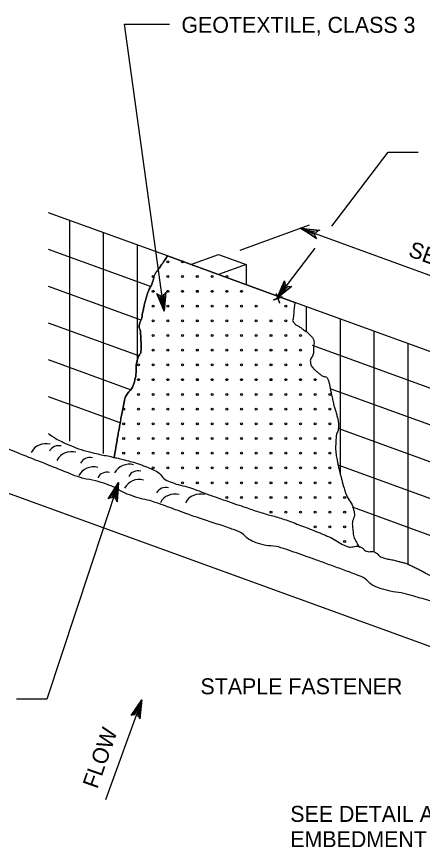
# Model space of a CAD drawing. Extents: x 636462 to 639049, y 299944 to 300538.
# Drawn here: x 636561.4 to 636637.5, y 300112.8 to 300268.7 of the extents above; entities that cross this region are included whole.
import ezdxf

# ---------------------------------------------------------------- set-up
doc = ezdxf.new("R2010")
doc.units = 0
doc.layers.add('Default', color=7, linetype='Continuous')

msp = doc.modelspace()

# ---------------------------------------------------------------- linework, layer by layer
at = {"layer": 'Default'}
for p, q in [((636589.69, 300223.81), (636567.43, 300231.91)), ((636571.32, 300230.5), (636571.32, 300189.06)), ((636571.32, 300230.5), (636571.32, 300230.5)), ((636603.35, 300224.92), (636616.34, 300229.64)), ((636577.67, 300228.19), (636577.67, 300186.75)), ((636577.67, 300228.19), (636577.67, 300228.19)), ((636584.01, 300225.88), (636584.01, 300203.89)), ((636584.01, 300225.88), (636584.01, 300225.88)), ((636586.55, 300218.05), (636567.43, 300225.01)), ((636613.62, 300215.1), (636589.69, 300223.81)), ((636589.69, 300223.81), (636613.62, 300215.1)), ((636590.36, 300223.57), (636590.36, 300223.57)), ((636596.71, 300221.26), (636596.71, 300221.26)), ((636604.5, 300222.2), (636604.5, 300218.42)), ((636584.79, 300211.78), (636567.43, 300218.1)), ((636603.05, 300218.95), (636603.05, 300218.95)), ((636609.4, 300216.64), (636609.4, 300216.64)), ((636689.45, 300187.5), (636613.62, 300215.1)), ((636615.75, 300214.33), (636615.75, 300209.52)), ((636615.75, 300214.33), (636615.75, 300214.33)), ((636622.09, 300212.02), (636622.09, 300182.98)), ((636622.09, 300212.02), (636622.09, 300212.02)), ((636584.34, 300205.04), (636567.43, 300211.19)), ((636628.44, 300209.71), (636628.44, 300168.26)), ((636628.44, 300209.71), (636628.44, 300209.71)), ((636689.45, 300180.59), (636616.89, 300207)), ((636634.79, 300207.4), (636634.79, 300165.96)), ((636634.79, 300207.4), (636634.79, 300207.4)), ((636582.75, 300198.71), (636567.43, 300204.29)), ((636689.45, 300173.69), (636620.24, 300198.88)), ((636580.84, 300192.5), (636567.43, 300197.38)), ((636689.45, 300166.78), (636621.71, 300191.44)), ((636689.45, 300159.87), (636621.74, 300184.52)), ((636673.8, 300137.8), (636559.57, 300179.37)), ((636689.45, 300152.97), (636624.4, 300176.65)), ((636584.92, 300140.52), (636578.08, 300121.72))]:
    msp.add_line(p, q, dxfattribs=at)
for points in [[(636589.08, 300213.44), (636581.64, 300267.32), (636590.08, 300267.32)], [(636620.53, 300229.41), (636631.08, 300243.32), (636636.75, 300243.32)], [(636614.68, 300229.04), (636645.53, 300217.77)], [(636617.5, 300227.34), (636617.67, 300227.03), (636614.68, 300229.04), (636617.5, 300227.34), (636617.44, 300227.75), (636614.68, 300229.04), (636617.61, 300228.25), (636617.91, 300228.54), (636614.68, 300229.04), (636618.27, 300228.68), (636617.91, 300228.54)], [(636610.23, 300215.82), (636617.41, 300225.29)], [(636612.72, 300217.99), (636613.06, 300218.07), (636610.23, 300215.82), (636612.72, 300217.99), (636612.3, 300218.06), (636610.23, 300215.82), (636611.88, 300218.38), (636611.7, 300218.75), (636610.23, 300215.82), (636611.67, 300219.13), (636611.7, 300218.75)], [(636589.25, 300216.73), (636589.43, 300217.03), (636589.08, 300213.44), (636589.25, 300216.73), (636588.91, 300216.49), (636589.08, 300213.44), (636588.39, 300216.41), (636587.99, 300216.53), (636589.08, 300213.44), (636587.7, 300216.78), (636587.99, 300216.53)], [(636580.53, 300181.28), (636567.1, 300140.64), (636561.43, 300140.64)], [(636578.9, 300178.42), (636578.6, 300178.24), (636580.53, 300181.28), (636578.9, 300178.42), (636579.31, 300178.49), (636580.53, 300181.28), (636579.81, 300178.33), (636580.11, 300178.03), (636580.53, 300181.28), (636580.26, 300177.69), (636580.11, 300178.03)], [(636583.2, 300137.71), (636582.9, 300137.54), (636584.92, 300140.52), (636583.2, 300137.71), (636583.62, 300137.77), (636584.92, 300140.52), (636584.11, 300137.59), (636584.4, 300137.29), (636584.92, 300140.52), (636584.54, 300136.94), (636584.4, 300137.29)]]:
    msp.add_lwpolyline(points, dxfattribs=at)
msp.add_lwpolyline([(636599.3, 300220.31), (636594.11, 300222.2), (636599.3, 300224.09), (636604.5, 300222.2)], close=True, dxfattribs=at)
for centre in [(636589.79, 300222.7), (636592.55, 300222.7), (636587.03, 300219.93), (636589.79, 300219.93), (636592.55, 300219.93), (636595.31, 300219.93), (636598.08, 300219.93), (636600.84, 300219.93), (636587.03, 300217.17), (636589.79, 300217.17), (636592.55, 300217.17), (636595.31, 300217.17), (636598.08, 300217.17), (636600.84, 300217.17), (636603.6, 300217.17), (636587.03, 300214.41), (636589.79, 300214.41), (636592.55, 300214.41), (636595.31, 300214.41), (636598.08, 300214.41), (636600.84, 300214.41), (636603.6, 300214.41), (636606.37, 300214.41), (636611.89, 300214.41), (636587.03, 300211.65), (636589.79, 300211.65), (636592.55, 300211.65), (636595.31, 300211.65), (636598.08, 300211.65), (636600.84, 300211.65), (636603.6, 300211.65), (636606.37, 300211.65), (636609.13, 300211.65), (636611.89, 300211.65), (636587.03, 300208.88), (636589.79, 300208.88), (636592.55, 300208.88), (636595.31, 300208.88), (636598.08, 300208.88), (636600.84, 300208.88), (636603.6, 300208.88), (636606.37, 300208.88), (636609.13, 300208.88), (636611.89, 300208.88), (636614.65, 300208.88), (636587.03, 300206.12), (636589.79, 300206.12), (636592.55, 300206.12), (636595.31, 300206.12), (636598.08, 300206.12), (636600.84, 300206.12), (636603.6, 300206.12), (636606.37, 300206.12), (636609.13, 300206.12), (636611.89, 300206.12), (636614.65, 300206.12), (636584.26, 300203.36), (636587.03, 300203.36), (636589.79, 300203.36), (636592.55, 300203.36), (636595.31, 300203.36), (636598.08, 300203.36), (636600.84, 300203.36), (636603.6, 300203.36), (636606.37, 300203.36), (636609.13, 300203.36), (636611.89, 300203.36), (636614.65, 300203.36), (636584.26, 300200.59), (636587.03, 300200.59), (636589.79, 300200.59), (636592.55, 300200.59), (636595.31, 300200.59), (636598.08, 300200.59), (636600.84, 300200.59), (636603.6, 300200.59), (636606.37, 300200.59), (636609.13, 300200.59), (636611.89, 300200.59), (636614.65, 300200.59), (636617.42, 300200.59), (636584.26, 300197.83), (636587.03, 300197.83), (636589.79, 300197.83), (636592.55, 300197.83), (636595.31, 300197.83), (636598.08, 300197.83), (636600.84, 300197.83), (636603.6, 300197.83), (636606.37, 300197.83), (636609.13, 300197.83), (636611.89, 300197.83), (636614.65, 300197.83), (636617.42, 300197.83), (636620.18, 300197.83), (636581.5, 300195.07), (636584.26, 300195.07), (636587.03, 300195.07), (636589.79, 300195.07), (636592.55, 300195.07), (636595.31, 300195.07), (636598.08, 300195.07), (636600.84, 300195.07), (636603.6, 300195.07), (636606.37, 300195.07), (636609.13, 300195.07), (636611.89, 300195.07), (636614.65, 300195.07), (636617.42, 300195.07), (636620.18, 300195.07), (636581.5, 300192.31), (636584.26, 300192.31), (636587.03, 300192.31), (636589.79, 300192.31), (636592.55, 300192.31), (636595.31, 300192.31), (636598.08, 300192.31), (636600.84, 300192.31), (636603.6, 300192.31), (636606.37, 300192.31), (636609.13, 300192.31), (636611.89, 300192.31), (636614.65, 300192.31), (636617.42, 300192.31), (636620.18, 300192.31), (636581.5, 300189.54), (636584.26, 300189.54), (636587.03, 300189.54), (636589.79, 300189.54), (636592.55, 300189.54), (636595.31, 300189.54), (636598.08, 300189.54), (636600.84, 300189.54), (636603.6, 300189.54), (636606.37, 300189.54), (636609.13, 300189.54), (636611.89, 300189.54), (636614.65, 300189.54), (636617.42, 300189.54), (636620.18, 300189.54), (636581.5, 300186.78), (636584.26, 300186.78), (636587.03, 300186.78), (636589.79, 300186.78), (636592.55, 300186.78), (636595.31, 300186.78), (636598.08, 300186.78), (636600.84, 300186.78), (636603.6, 300186.78), (636606.37, 300186.78), (636609.13, 300186.78), (636611.89, 300186.78), (636614.65, 300186.78), (636617.42, 300186.78), (636620.18, 300186.78), (636587.03, 300184.02), (636589.79, 300184.02), (636592.55, 300184.02), (636595.31, 300184.02), (636598.08, 300184.02), (636600.84, 300184.02), (636603.6, 300184.02), (636606.37, 300184.02), (636609.13, 300184.02), (636611.89, 300184.02), (636614.65, 300184.02), (636617.42, 300184.02), (636620.18, 300184.02), (636592.55, 300181.25), (636595.31, 300181.25), (636598.08, 300181.25), (636600.84, 300181.25), (636603.6, 300181.25), (636606.37, 300181.25), (636609.13, 300181.25), (636611.89, 300181.25), (636614.65, 300181.25), (636617.42, 300181.25), (636620.18, 300181.25), (636600.84, 300178.49), (636603.6, 300178.49), (636606.37, 300178.49), (636609.13, 300178.49), (636611.89, 300178.49), (636614.65, 300178.49), (636617.42, 300178.49), (636620.18, 300178.49), (636622.94, 300178.49), (636609.13, 300175.73), (636611.89, 300175.73), (636614.65, 300175.73), (636617.42, 300175.73), (636620.18, 300175.73), (636622.94, 300175.73), (636617.42, 300172.97), (636620.18, 300172.97), (636622.94, 300172.97), (636622.94, 300170.2)]:
    msp.add_circle(centre, 0.184, dxfattribs=at)
for centre, radius, start, end in [((636566.89, 300185.46), 3.11, 74.7812, 151.5772), ((636569.3, 300186.25), 1.96, 75.3044, 152.6271), ((636571.73, 300183.97), 3.11, 74.7812, 151.5772), ((636575.14, 300184.01), 1.96, 75.3044, 152.6271), ((636575.83, 300181.11), 3.11, 74.7812, 151.5772), ((636582.54, 300181.61), 3.11, 74.7812, 151.5772), ((636584.2, 300181.53), 1.96, 75.3044, 152.6271), ((636578.37, 300181.28), 1.96, 75.3044, 152.6271), ((636584.4, 300178.75), 3.11, 74.7812, 151.5772), ((636589.42, 300178.42), 1.96, 75.3044, 152.6271), ((636591.11, 300176.02), 3.11, 74.7812, 151.5772), ((636595.83, 300176.02), 3.11, 74.7812, 151.5772)]:
    msp.add_arc(centre, radius, start, end, dxfattribs=at)
for points in [[(636589.69, 300223.81), (636589.25, 300223.09), (636588.77, 300222.4), (636588.3, 300221.7), (636588.02, 300221.27), (636587.65, 300220.89), (636587.39, 300220.44), (636587.13, 300219.99), (636587.12, 300219.44), (636586.93, 300218.95), (636586.62, 300218.15), (636586.17, 300217.39), (636585.9, 300216.56), (636585.63, 300215.69), (636585.42, 300214.81), (636585.22, 300213.93), (636585.09, 300213.36), (636585, 300212.78), (636584.88, 300212.21), (636584.77, 300211.71), (636584.46, 300211.23), (636584.42, 300210.73), (636584.38, 300210.31), (636584.62, 300209.89), (636584.65, 300209.47), (636584.69, 300208.82), (636584.73, 300208.17), (636584.76, 300207.53), (636584.78, 300207.07), (636584.8, 300206.61), (636584.76, 300206.16), (636584.71, 300205.51), (636584.23, 300204.95), (636584.07, 300204.33), (636583.75, 300203), (636583.89, 300201.53), (636583.5, 300200.21), (636583.1, 300198.83), (636581.84, 300197.75), (636581.56, 300196.33), (636581.33, 300195.11), (636581.09, 300193.89), (636580.88, 300192.67), (636580.69, 300191.61), (636580.49, 300190.54), (636580.31, 300189.47), (636580.1, 300188.32), (636579.91, 300187.16), (636579.72, 300186)], [(636579.72, 300186), (636579.91, 300187.16), (636580.1, 300188.31), (636580.31, 300189.47), (636580.49, 300190.54), (636580.69, 300191.6), (636580.88, 300192.67), (636581.1, 300193.89), (636581.33, 300195.11), (636581.56, 300196.33), (636581.84, 300197.75), (636583.1, 300198.83), (636583.5, 300200.21), (636583.89, 300201.53), (636583.75, 300203), (636584.07, 300204.33), (636584.23, 300204.95), (636584.71, 300205.51), (636584.76, 300206.16), (636584.8, 300206.61), (636584.78, 300207.07), (636584.76, 300207.53), (636584.73, 300208.17), (636584.69, 300208.82), (636584.65, 300209.47), (636584.62, 300209.89), (636584.38, 300210.31), (636584.42, 300210.73), (636584.46, 300211.23), (636584.77, 300211.71), (636584.88, 300212.21), (636585, 300212.78), (636585.09, 300213.36), (636585.22, 300213.93), (636585.42, 300214.81), (636585.63, 300215.69), (636585.9, 300216.55), (636586.17, 300217.38), (636586.62, 300218.15), (636586.93, 300218.95), (636587.12, 300219.44), (636587.13, 300219.99), (636587.39, 300220.44), (636587.65, 300220.89), (636588.02, 300221.27), (636588.3, 300221.7), (636588.77, 300222.4), (636589.25, 300223.09), (636589.69, 300223.81)], [(636613.62, 300215.1), (636613.46, 300214.18), (636613.42, 300213.25), (636613.33, 300212.33), (636613.3, 300212.02), (636613.11, 300211.68), (636613.33, 300211.41), (636613.77, 300210.85), (636614.32, 300210.66), (636614.81, 300210.27), (636615.39, 300209.82), (636615.97, 300209.49), (636616.53, 300208.9), (636617.3, 300208.09), (636617.12, 300206.9), (636617.1, 300205.93), (636617.08, 300205.2), (636616.45, 300204.48), (636616.53, 300203.76), (636616.56, 300203.48), (636616.67, 300203.2), (636616.87, 300202.95), (636617.34, 300202.39), (636617.84, 300202.01), (636618.36, 300201.59), (636618.82, 300201.2), (636619.65, 300201.13), (636619.84, 300200.56), (636620.06, 300199.92), (636620.16, 300199.26), (636620.3, 300198.61), (636620.49, 300197.74), (636620.68, 300196.86), (636620.87, 300195.99), (636621.05, 300195.17), (636621.35, 300194.4), (636621.56, 300193.59), (636621.71, 300192.99), (636621.79, 300192.36), (636621.79, 300191.76), (636621.78, 300191.07), (636621.37, 300190.39), (636621.33, 300189.7), (636621.26, 300188.46), (636621.21, 300187.17), (636621.44, 300185.93), (636621.58, 300185.2), (636621.72, 300184.48), (636621.9, 300183.76), (636622.05, 300183.15), (636622.2, 300182.54), (636622.36, 300181.93), (636622.53, 300181.24), (636622.73, 300180.56), (636622.93, 300179.87), (636623.31, 300178.55), (636624.29, 300177.44), (636624.64, 300176.1), (636624.91, 300175.1), (636624.31, 300174.04), (636624.41, 300173.02), (636624.51, 300172.05), (636624.6, 300171.11), (636625.1, 300170.16), (636625.31, 300169.76), (636625.66, 300169.08), (636625.89, 300169.19)], [(636613.62, 300215.1), (636613.46, 300214.18), (636613.42, 300213.25), (636613.33, 300212.33), (636613.3, 300212.02), (636613.11, 300211.68), (636613.33, 300211.41), (636613.77, 300210.85), (636614.32, 300210.66), (636614.81, 300210.27), (636615.39, 300209.82), (636615.97, 300209.49), (636616.53, 300208.9), (636617.3, 300208.09), (636617.12, 300206.9), (636617.1, 300205.93), (636617.08, 300205.2), (636616.45, 300204.48), (636616.53, 300203.76), (636616.56, 300203.48), (636616.67, 300203.2), (636616.87, 300202.95), (636617.34, 300202.39), (636617.84, 300202.01), (636618.36, 300201.59), (636618.82, 300201.2), (636619.65, 300201.13), (636619.84, 300200.56), (636620.06, 300199.92), (636620.16, 300199.26), (636620.3, 300198.61), (636620.49, 300197.74), (636620.68, 300196.86), (636620.87, 300195.99), (636621.05, 300195.17), (636621.35, 300194.4), (636621.56, 300193.58), (636621.71, 300192.98), (636621.79, 300192.36), (636621.79, 300191.76), (636621.78, 300191.07), (636621.37, 300190.39), (636621.33, 300189.7), (636621.26, 300188.46), (636621.21, 300187.17), (636621.44, 300185.93), (636621.58, 300185.2), (636621.72, 300184.48), (636621.9, 300183.76), (636622.05, 300183.15), (636622.2, 300182.54), (636622.36, 300181.93), (636622.53, 300181.24), (636622.73, 300180.56), (636622.93, 300179.87), (636623.31, 300178.55), (636624.29, 300177.44), (636624.64, 300176.1), (636624.91, 300175.1), (636624.31, 300174.04), (636624.41, 300173.02), (636624.51, 300172.05), (636624.6, 300171.11), (636625.1, 300170.16), (636625.31, 300169.76), (636625.66, 300169.08), (636625.89, 300169.19)], [(636567.43, 300190.47), (636568.26, 300189.86), (636569.1, 300189.31), (636570.04, 300188.89), (636572.02, 300188), (636574.04, 300187.26), (636576.13, 300186.78), (636577.32, 300186.5), (636578.52, 300186.28), (636579.72, 300186), (636580.68, 300185.78), (636581.63, 300185.53), (636582.59, 300185.29), (636584.13, 300184.89), (636585.61, 300184.31), (636587.06, 300183.67), (636588.23, 300183.16), (636588.97, 300181.88), (636590.17, 300181.43), (636591.75, 300180.84), (636593.43, 300180.54), (636595.01, 300179.94), (636595.88, 300179.62), (636596.74, 300179.26), (636597.62, 300178.95), (636599.64, 300178.24), (636601.67, 300177.53), (636603.7, 300176.84), (636604.94, 300176.42), (636606.19, 300176), (636607.43, 300175.6), (636608.58, 300175.22), (636609.77, 300174.98), (636610.91, 300174.6), (636612.29, 300174.15), (636613.65, 300173.63), (636615.01, 300173.11), (636616.47, 300172.56), (636617.91, 300171.96), (636619.36, 300171.37), (636620.69, 300170.83), (636621.89, 300169.96), (636623.21, 300169.39), (636624.02, 300169.03), (636625.06, 300169.46), (636625.89, 300169.19), (636626.33, 300169.05), (636626.63, 300168.54), (636627.06, 300168.39), (636627.48, 300168.24), (636628.02, 300168.43), (636628.44, 300168.26), (636629.06, 300168.02), (636629.51, 300167.33), (636630.16, 300167.15), (636631.06, 300166.9), (636632, 300166.78), (636632.9, 300166.53), (636633.53, 300166.35), (636634.17, 300166.2), (636634.79, 300165.96), (636635.55, 300165.65), (636636.27, 300165.27), (636637, 300164.91), (636637.71, 300164.56), (636638.38, 300164.12), (636639.11, 300163.8), (636639.73, 300163.52), (636640.49, 300163.86), (636641.13, 300163.65), (636641.99, 300163.37), (636642.85, 300163.09), (636643.7, 300162.8), (636644.33, 300162.6), (636644.95, 300162.39), (636645.57, 300162.18), (636646.23, 300161.96), (636646.83, 300161.58), (636647.48, 300161.34), (636647.97, 300161.15), (636648.55, 300161.34), (636649.05, 300161.19), (636649.69, 300160.99), (636650.16, 300160.3), (636650.78, 300160.07), (636651.39, 300159.84), (636652.18, 300160.1), (636652.77, 300159.82), (636653.17, 300159.64), (636653.42, 300159.2), (636653.83, 300159.03), (636654.7, 300158.66), (636655.59, 300158.34), (636656.5, 300158.08), (636657.07, 300157.92), (636657.7, 300157.96), (636658.24, 300157.71), (636658.89, 300157.4), (636659.52, 300157.04), (636660.17, 300156.72)], [(636673.8, 300146.09), (636673.35, 300146.57), (636672.87, 300147.01), (636672.27, 300147.27), (636670.81, 300147.93), (636669.14, 300147.81), (636667.68, 300148.39), (636665.76, 300149.16), (636663.92, 300150.19), (636661.96, 300150.88), (636660.03, 300151.56), (636658.08, 300152.23), (636656.13, 300152.86), (636654.68, 300153.34), (636653.23, 300153.78), (636651.78, 300154.23), (636649.95, 300154.8), (636648.02, 300155.02), (636646.19, 300155.6), (636644.1, 300156.25), (636642.41, 300157.85), (636640.35, 300158.58), (636638.76, 300159.14), (636637.13, 300159.61), (636635.51, 300160.07), (636633.54, 300160.62), (636631.49, 300160.81), (636629.54, 300161.44), (636627.99, 300161.94), (636626.85, 300163.35), (636625.32, 300163.92), (636622.84, 300164.85), (636620.36, 300165.76), (636617.87, 300166.65), (636615.88, 300167.37), (636613.89, 300168.07), (636611.9, 300168.76), (636610.1, 300169.39), (636608.12, 300169.38), (636606.32, 300170.01), (636604.86, 300170.51), (636603.79, 300171.85), (636602.34, 300172.37), (636599.42, 300173.4), (636596.44, 300174.3), (636593.52, 300175.35), (636591.7, 300176), (636589.88, 300176.69), (636588.06, 300177.34), (636586.39, 300177.93), (636584.64, 300178.26), (636582.96, 300178.83), (636581.37, 300179.37), (636579.95, 300180.38), (636578.36, 300180.94), (636576.22, 300181.7), (636573.9, 300181.96), (636571.78, 300182.8), (636570.33, 300183.38), (636568.89, 300183.96), (636567.44, 300184.54), (636564.81, 300185.58), (636562.19, 300186.62), (636559.57, 300187.66)]]:
    msp.add_open_spline(points, degree=3, dxfattribs=at)

# ---------------------------------------------------------------- texts
for s, p in [('GEOTEXTILE, CLASS 3', (636592.33, 300265.69)), ('STAPLE FASTENER', (636595.9, 300141.54)), ('SEE DETAIL A FOR', (636612.74, 300117.6)), ('EMBEDMENT DETAILS', (636612.74, 300112.85))]:
    msp.add_text(s, height=2.998, dxfattribs=at).set_placement(p)
for s, height, rotation, p in [('SEE TABLE A', 2.998, 340, (636634.69, 300223.83)), ('+', 2.83, 20, (636609.86, 300214.19)), ('FLOW', 2.998, 70.6533, (636576.55, 300123.66))]:
    msp.add_text(s, height=height, rotation=rotation, dxfattribs=at).set_placement(p)

doc.saveas('drawing.dxf')
